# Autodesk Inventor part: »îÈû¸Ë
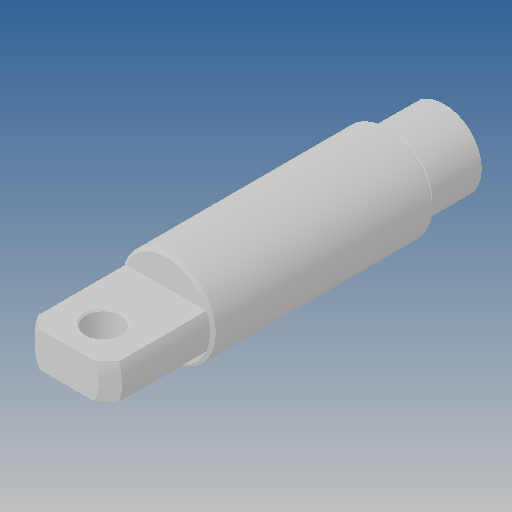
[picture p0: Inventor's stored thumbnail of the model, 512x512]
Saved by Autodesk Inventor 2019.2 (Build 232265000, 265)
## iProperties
Created: 2013-07
Part Number: »îÈû¸Ë
Material: Ogólny
Document SubType Name: Modeling
Designer: CADENGINEERING4
Density: 1 g/cm^3
Appearance: Domyślna
Author: CADENGINEERING4
Revision Number: ÈÎºÎ
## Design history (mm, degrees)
feature "µ¹½Ç1"
node "Bryła1"
